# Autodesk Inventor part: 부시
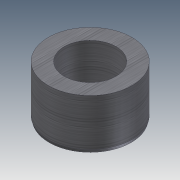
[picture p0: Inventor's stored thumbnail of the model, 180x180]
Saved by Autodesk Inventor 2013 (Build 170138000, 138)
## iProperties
Company: 한국ATC센터
Created: 2014-11
Part Number: 부시
Document SubType Name: Modeling
Designer: KYOUNG IL JANG
Density: 7.86 g/cm^3
Material: 강, 연강
Mass: 167.601 g
Surface Area: 70.0223 cm^2
Volume: 21.3233 cm^3
Author: KYOUNG IL JANG
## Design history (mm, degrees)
sketch "스케치1"
  geometry: C1 r 21 at (0, 0); C2 r 13 at (0, 0); 1 further point
  constraints: 2 centre point, 2 coincident
  dimensions: "d4" = 26 diameter of C2; "d5" = 42 diameter of C1
extrude "돌출1" new body sketch "스케치1" distance "d0" = 25; taper "d1" = 0 deg
chamfer "모따기1" distance "d6" = 1.5; stored, may be unused: second distance "d7" = 2, angle "d8" = 15 deg
node "솔리드1"
